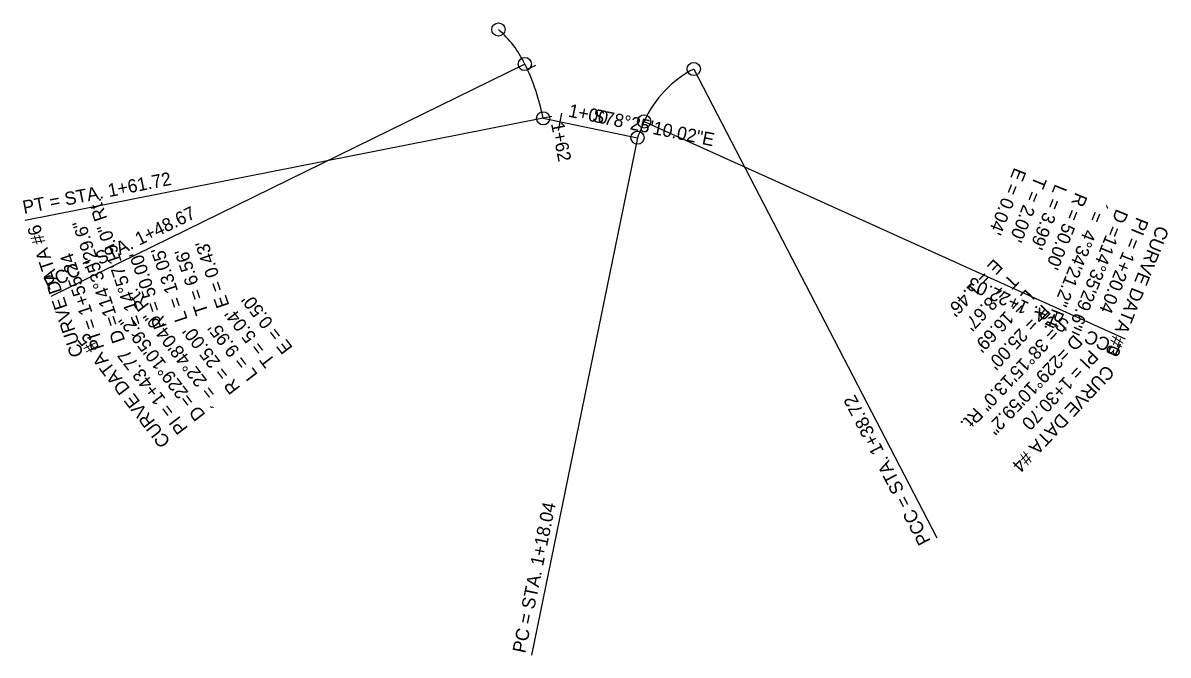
# Model space of a CAD drawing. Extents: x 1158784 to 1165006, y 610007 to 611539.
# Drawn here: x 1160413.2 to 1160673.6, y 610879.2 to 611022.9 of the extents above; entities that cross this region are included whole.
import ezdxf

# ---------------------------------------------------------------- set-up
doc = ezdxf.new("R2010")
doc.units = 0
for name, color, linetype in [('D_Roadway_Centerline', 7, 'Continuous'), ('D_Roadway_Centerline_Bearings', 7, 'Continuous'), ('D_Roadway_Centerline_CurveData', 7, 'Continuous'), ('D_Roadway_Centerline_Flags', 7, 'Continuous'), ('D_Roadway_Centerline_Text', 7, 'Continuous')]:
    doc.layers.add(name, color=color, linetype=linetype)

msp = doc.modelspace()

# ---------------------------------------------------------------- linework, layer by layer
at = {"layer": 'D_Roadway_Centerline'}
msp.add_line((1160531.52, 611001.19), (1160552.99, 610996.79), dxfattribs=at)
for centre, radius, start, end in [((1160504.92, 611002.52), 25, 26.1078, 48.9089), ((1160482.47, 610991.52), 50, 11.1525, 26.1078), ((1160577.27, 610990.2), 25, 117.4276, 155.6812), ((1160600.05, 610979.9), 50, 155.6812, 160.2537)]:
    msp.add_arc(centre, radius, start, end, dxfattribs=at)
at = {"layer": 'D_Roadway_Centerline_Flags'}
for points in [[(1160527.37, 611013.53), (1160419.61, 610960.72)], [(1160565.76, 611012.39), (1160621.03, 610905.88)], [(1160531.52, 611001.19), (1160413.79, 610977.98)], [(1160554.49, 611000.49), (1160663.84, 610951.07)], [(1160552.99, 610996.79), (1160528.9, 610879.24)]]:
    msp.add_lwpolyline(points, dxfattribs=at)
for centre in [(1160521.35, 611021.37), (1160527.37, 611013.53), (1160565.76, 611012.39), (1160531.52, 611001.19), (1160531.52, 611001.19), (1160554.49, 611000.49), (1160552.99, 610996.79)]:
    msp.add_circle(centre, 1.5, dxfattribs=at)
at = {"layer": 'D_Roadway_Centerline_Text'}
for points in [[(1160529.75, 611013.16), (1160527.93, 611012.33)], [(1160533.49, 611001.58), (1160529.56, 611000.81)], [(1160533.49, 611001.58), (1160529.56, 611000.81)], [(1160535.72, 611002.38), (1160534.92, 610998.46)]]:
    msp.add_lwpolyline(points, dxfattribs=at)

# ---------------------------------------------------------------- texts
at = {"layer": 'D_Roadway_Centerline_Bearings'}
msp.add_text('S78%%d25\'10.02"E', height=3, rotation=348.4194, dxfattribs=at).set_placement((1160542.56, 611000.46))
at = {"layer": 'D_Roadway_Centerline_CurveData'}
for s, rotation, p in [("E = 0.04'", 247.9674, (1160638.68, 610990.16)), ("T = 2.00'", 247.9674, (1160643.32, 610988.28)), ("L = 3.99'", 247.9674, (1160647.95, 610986.41)), ('´ = 14%%d57\'19.0" Rt.', 108.6302, (1160441.27, 610952.31)), ("R = 50.00'", 247.9674, (1160652.59, 610984.53)), ('´ =  4%%d34\'21.2" Rt.', 247.9674, (1160657.22, 610982.66)), ('D =114%%d35\'29.6"', 247.9674, (1160661.86, 610980.78)), ('CURVE DATA #6', 108.6302, (1160427.05, 610947.51)), ('D =114%%d35\'29.6"', 108.6302, (1160436.53, 610950.71)), ('PI = 1+20.04', 247.9674, (1160666.49, 610978.91)), ('CURVE DATA #3', 247.9674, (1160671.13, 610977.03)), ("E = 0.43'", 108.6302, (1160460.22, 610958.7)), ('PI = 1+55.24', 108.6302, (1160431.79, 610949.11)), ("R = 50.00'", 108.6302, (1160446, 610953.9)), ("L = 13.05'", 108.6302, (1160450.74, 610955.5)), ("T = 6.56'", 108.6302, (1160455.48, 610957.1)), ("E = 1.46'", 226.5544, (1160634.1, 610969.43)), ("T = 8.67'", 226.5544, (1160637.73, 610965.99)), ('´ = 22%%d48\'04.0" Rt.', 127.5083, (1160458.85, 610936.91)), ("L = 16.69'", 226.5544, (1160641.36, 610962.55)), ("E = 0.50'", 127.5083, (1160474.71, 610949.09)), ("R = 25.00'", 226.5544, (1160644.99, 610959.11)), ("T = 5.04'", 127.5083, (1160470.75, 610946.04)), ('D =229%%d10\'59.2"', 127.5083, (1160454.88, 610933.87)), ("L = 9.95'", 127.5083, (1160466.78, 610943)), ('´ = 38%%d15\'13.0" Rt.', 226.5544, (1160648.62, 610955.68)), ('CURVE DATA #5', 127.5083, (1160446.95, 610927.78)), ("R = 25.00'", 127.5083, (1160462.81, 610939.95)), ('D =229%%d10\'59.2"', 226.5544, (1160652.25, 610952.24)), ('PI = 1+30.70', 226.5544, (1160655.88, 610948.8)), ('PI = 1+43.77', 127.5083, (1160450.91, 610930.82)), ('CURVE DATA #4', 226.5544, (1160659.51, 610945.36))]:
    msp.add_text(s, height=3, rotation=rotation, dxfattribs=at).set_placement(p)
at = {"layer": 'D_Roadway_Centerline_Flags'}
for s, rotation, p in [('PT = STA. 1+61.72', 11.1525, (1160413.5, 610979.46)), ('PCC = STA. 1+48.67', 26.1078, (1160418.95, 610962.07)), ('PCC = STA. 1+22.03', 155.6812, (1160663.23, 610949.71)), ('PCC = STA. 1+38.72', 117.4276, (1160619.7, 610905.18)), ('PC = STA. 1+18.04', 78.4194, (1160527.44, 610879.54))]:
    msp.add_text(s, height=3, rotation=rotation, dxfattribs=at).set_placement(p)
at = {"layer": 'D_Roadway_Centerline_Text'}
for s, rotation, p in [('1+00', 348.4194, (1160537.09, 611001.59)), ('1+62', 281.1525, (1160533.28, 611000.01)), ('1+62', 281.1525, (1160533.28, 611000.01))]:
    msp.add_text(s, height=3, rotation=rotation, dxfattribs=at).set_placement(p)

doc.saveas('drawing.dxf')
